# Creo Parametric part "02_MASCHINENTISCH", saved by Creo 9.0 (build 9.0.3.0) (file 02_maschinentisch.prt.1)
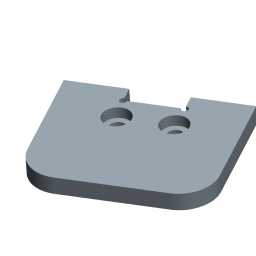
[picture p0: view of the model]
Materials in the file: STAHL

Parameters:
  SCHRAUBEN_GROESSE = "M4x.7"
  METRISCH = "JA"
  WERKSTOFF = "Stahl"
  ERSTELLER = "ARINDA"
  BENENNUNG = "Bemaßung"
  TEILETYP = "K"
  PTC_MASTER_MATERIAL = "STAHL"
  PTC_MATERIAL_DESCRIPTION = "allgemeiner Baustahl; unberuhigt"
  SELECT_EN_NAME = "S235JRG2"
  SELECT_DIN_NAME = "RSt37-2"
  SELECT_DIN_NUMBER = "1.0038"
  SELECT_ASTM_NAME = "A 283 M Grade 2"
  MATERIAL_GROUP = "ME_ST_Baustahl"
  STANDARD_EN_DELIVERYSPEC = "DIN EN 10025"
  STANDARD_DIN_DELIVERYSPEC = "DIN 17100"

Other parameters: ANSENKDURCHMESSER, ANSENKTIEFE, BOHR_DURCHM, MASSE

Created from: MASCHINENTISCH.PRT

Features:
  1. coordinate system
  2. datum plane "RECHTS_Y-Z"
  3. datum plane "OBEN_X-Z"
  4. datum plane "VORNE_X-Y"
  5. datum axis
  6. datum axis
  7. datum axis
  8. datum point "PNT0"
  9. protrusion
  10. cut
  11. cut
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
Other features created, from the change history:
  planar section "A"
  feature "Kopieren 1"

Other named items: MASCHINENTISCH, NUT, FREIMACHUNG, BEFESTIGUNG, A_X, A_Y, A_Z, CS0, GP0, GP1, GP2, GP3, GP4

Layers: 01_ACHSEN, 01_ACHSEN_STD, 01_EBENEN, 01_EBENEN_STD, 01_KOORDSYS_STD, 01_KURVEN, 01_PUNKTE_STD, FLAECHEN, SAMMELFLÄCHEN, VOLUMENGEOMETRIE, XSEC_DATUMS

Notes: M4x.7 | LÖSCHEN |  BOHREN (  | 4.500 | DURCH |   -(  |  ) BOHRUNG

Surfaces: 11 plane, 10 cylinder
